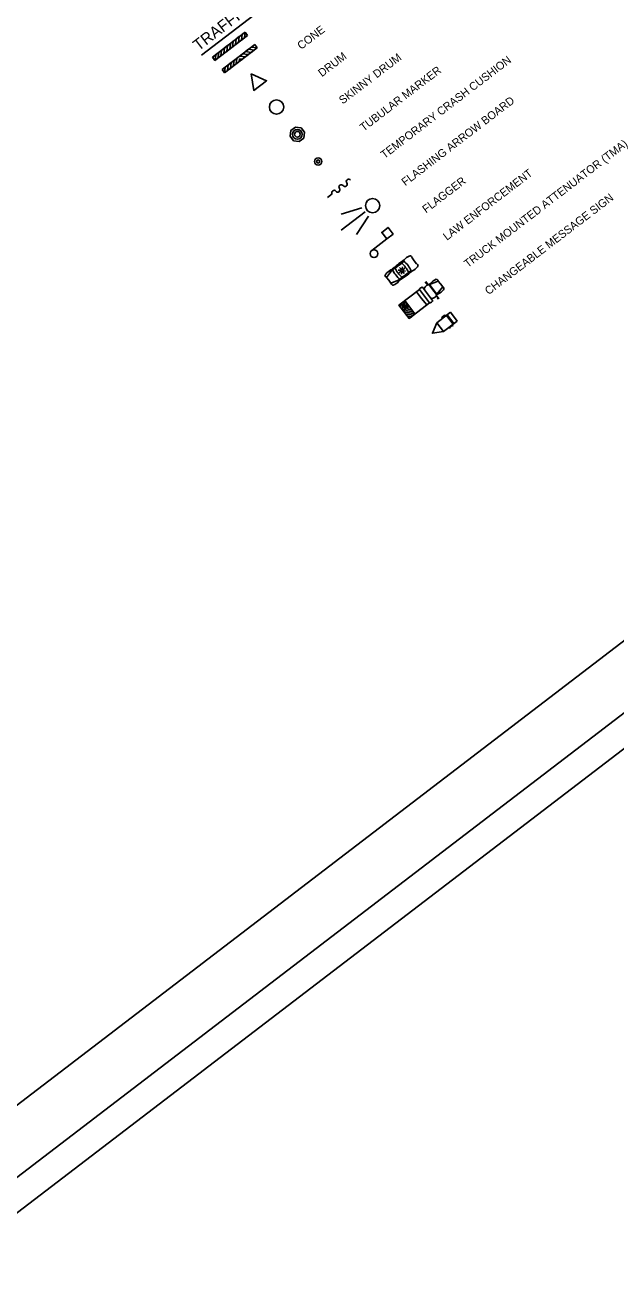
# Model space of a CAD drawing. Extents: x -642 to 2005, y -4412 to 1950.
# Drawn here: x 844 to 1361, y 126 to 1222 of the extents above; entities that cross this region are included whole.
import ezdxf

# ---------------------------------------------------------------- set-up
doc = ezdxf.new("R2010")
doc.units = 0
for name, color, linetype in [('DEV BORDER CELL', 7, 'Continuous'), ('Scratch_Level_0', 7, 'Continuous'), ('Sheet Plot Border Outside CELL', 7, 'Continuous')]:
    doc.layers.add(name, color=color, linetype=linetype)

msp = doc.modelspace()

# ---------------------------------------------------------------- linework, layer by layer
at = {"layer": 'DEV BORDER CELL'}
for p, q in [((998.1, 1195.3), (1161.9, 1320.5)), ((1007.8, 1193.5), (1036.3, 1215.3)), ((1038.5, 1212.5), (1009.9, 1190.6)), ((1022.8, 1200.4), (1023.4, 1205.4)), ((1023.4, 1205.4), (1026, 1207.4)), ((1026, 1207.4), (1025.4, 1202.4)), ((1028, 1204.4), (1028.6, 1209.4)), ((1030.5, 1206.3), (1028, 1204.4)), ((1028.6, 1209.4), (1031.2, 1211.4)), ((1031.2, 1211.4), (1030.5, 1206.3)), ((1033.1, 1208.3), (1033.8, 1213.4)), ((1035.7, 1210.3), (1033.1, 1208.3)), ((1033.8, 1213.4), (1036.3, 1215.3)), ((1036.3, 1215.3), (1035.7, 1210.3)), ((1036.3, 1215.3), (1038.5, 1212.5)), ((1007.8, 1193.5), (1010.6, 1195.6)), ((1010.6, 1195.6), (1010, 1190.6)), ((1012.5, 1192.6), (1013.2, 1197.6)), ((1015.1, 1194.5), (1012.5, 1192.6)), ((1013.2, 1197.6), (1015.7, 1199.5)), ((1015.7, 1199.5), (1015.1, 1194.5)), ((1016.1, 1182.6), (1044.7, 1204.4)), ((1017.7, 1196.5), (1018.3, 1201.5)), ((1020.2, 1198.5), (1017.7, 1196.5)), ((1018.3, 1201.5), (1020.9, 1203.5)), ((1046.9, 1201.6), (1018.3, 1179.7)), ((1020.9, 1203.5), (1020.2, 1198.5)), ((1025.4, 1202.4), (1022.8, 1200.4)), ((1034.1, 1196.4), (1031.6, 1194.4)), ((1031.6, 1194.4), (1036.6, 1193.7)), ((1039.1, 1195.7), (1034.1, 1196.4)), ((1036.6, 1193.7), (1039.1, 1195.7)), ((1039.3, 1200.3), (1036.7, 1198.3)), ((1036.7, 1198.3), (1041.7, 1197.6)), ((1044.3, 1199.6), (1039.3, 1200.3)), ((1041.7, 1197.6), (1044.3, 1199.6)), ((1044.7, 1204.4), (1041.9, 1202.3)), ((1041.9, 1202.3), (1046.9, 1201.6)), ((1044.7, 1204.4), (1046.9, 1201.6)), ((1046.9, 1201.6), (1044.7, 1204.4)), ((1010, 1190.6), (1007.8, 1193.5)), ((1009.9, 1190.6), (1007.8, 1193.5)), ((1016.1, 1182.6), (1018.9, 1184.7)), ((1018.9, 1184.7), (1018.3, 1179.7)), ((1020.9, 1181.7), (1021.5, 1186.7)), ((1023.4, 1183.6), (1020.9, 1181.7)), ((1021.5, 1186.7), (1024.1, 1188.7)), ((1024.1, 1188.7), (1023.4, 1183.6)), ((1026, 1185.6), (1026.6, 1190.6)), ((1028.6, 1187.6), (1026, 1185.6)), ((1026.6, 1190.6), (1029.2, 1192.6)), ((1029.2, 1192.6), (1028.6, 1187.6)), ((1031.1, 1189.5), (1031.5, 1192.1)), ((1033.7, 1191.5), (1031.1, 1189.5)), ((1031.4, 1189.8), (1034, 1191.7)), ((1031.5, 1192.1), (1034, 1191.7)), ((1018.3, 1179.7), (1016.1, 1182.6)), ((1018.3, 1179.7), (1016.1, 1182.6)), ((1108.5, 1070.8), (1112.5, 1073.8)), ((1138.5, 1061.8), (1120.2, 1056)), ((1141.3, 1058.1), (1120.3, 1042)), ((1144.1, 1054.4), (1133.8, 1038.3)), ((1147, 1024.3), (1160.2, 1034.5)), ((1165.1, 1007.7), (1167.5, 1008.8)), ((1172.7, 1007.9), (1171.4, 1009.5)), ((1175, 1015.2), (1173.3, 1013.2)), ((1173.6, 1008.2), (1173.9, 1010.2)), ((1174.3, 1014.9), (1174.5, 1014.6)), ((1174.5, 1007.7), (1176.1, 1008.9)), ((1184.3, 1015.4), (1182.3, 1017.9)), ((1184.3, 1015.4), (1186.2, 1012.8)), ((1165.1, 1007.7), (1160, 1000.9)), ((1161.9, 998.3), (1160, 1000.9)), ((1161.9, 998.3), (1163.9, 995.8)), ((1171.8, 999), (1163.9, 995.8)), ((1172.2, 1007.1), (1170.2, 1007.3)), ((1172.4, 1006.1), (1170.8, 1004.9)), ((1171.8, 999), (1173.5, 1001)), ((1173.3, 1005.6), (1173, 1003.6)), ((1174.2, 1005.9), (1175.5, 1004.3)), ((1174.7, 1006.7), (1176.7, 1006.4)), ((1181.6, 1006.5), (1179.3, 1005.4)), ((1181, 1006.2), (1181.2, 1006)), ((1181, 1006.2), (1181.2, 1006)), ((1196.2, 994.3), (1194.1, 997.1)), ((1196.4, 994.4), (1194.3, 997.2)), ((1197.7, 994.5), (1205.3, 997.6)), ((1207.2, 995.1), (1205.3, 997.6)), ((1170.9, 976.5), (1188.8, 990.2)), ((1190.7, 982.5), (1186.3, 988.3)), ((1193.2, 984.4), (1188.8, 990.2)), ((1195.9, 986.5), (1191.5, 992.3)), ((1194.9, 995.5), (1193.8, 996.9)), ((1195.9, 986.5), (1200.3, 980.7)), ((1200.5, 990), (1197.3, 994.2)), ((1200.9, 990.3), (1197.7, 994.5)), ((1200.5, 990), (1203.7, 985.8)), ((1200.9, 990.3), (1204.1, 986.2)), ((1204.1, 986.2), (1209.1, 992.7)), ((1207.2, 995.1), (1209.1, 992.7)), ((1170.9, 976.5), (1172.9, 978)), ((1179.7, 965), (1170.9, 976.5)), ((1170.9, 976.5), (1172.6, 974.3)), ((1172.9, 978), (1172.6, 974.3)), ((1173.9, 972.5), (1174.5, 979.3)), ((1174.5, 979.3), (1176, 980.5)), ((1176, 980.5), (1175.3, 970.8)), ((1184.8, 968.9), (1176, 980.5)), ((1176.9, 972), (1177.4, 978.7)), ((1177.4, 978.7), (1178.7, 976.9)), ((1178.7, 976.9), (1178.5, 973.2)), ((1179.7, 965), (1197.6, 978.6)), ((1190.7, 982.5), (1195.2, 976.8)), ((1193.2, 984.4), (1197.6, 978.6)), ((1203.5, 984.7), (1205.6, 982)), ((1203.7, 984.9), (1205.8, 982.1)), ((1204.3, 983.2), (1205.4, 981.8)), ((1175.3, 970.8), (1173.9, 972.5)), ((1175.3, 970.8), (1184.8, 968.9)), ((1176.6, 969), (1175.3, 970.8)), ((1183.3, 967.7), (1176.6, 969)), ((1183.4, 970.7), (1176.9, 972)), ((1178, 967.2), (1179.7, 965)), ((1181.7, 966.5), (1178, 967.2)), ((1178.5, 973.2), (1182.1, 972.5)), ((1179.7, 965), (1181.7, 966.5)), ((1182.1, 972.5), (1183.4, 970.7)), ((1184.8, 968.9), (1183.3, 967.7)), ((1215.9, 970.3), (1204, 961.1)), ((1210.8, 967.7), (1208.3, 965.8)), ((1211.3, 967), (1208.8, 965.1)), ((1212.5, 967.6), (1218.4, 959.9)), ((1213.1, 968.1), (1219, 960.4)), ((1215.9, 970.3), (1221.8, 962.5)), ((1221.8, 962.5), (1215.9, 970.3)), ((1204, 961.1), (1200.3, 952.2)), ((1209.9, 953.4), (1200.3, 952.2)), ((1204, 961.1), (1209.9, 953.4)), ((1221.8, 962.5), (1209.9, 953.4)), ((1217.5, 958.9), (1215, 957))]:
    msp.add_line(p, q, dxfattribs=at)
for points in [[(1331.7, 1914.5), (140.1, 1003.4), (777.9, 169.3), (1969.5, 1080.4)], [(1041.6, 1178.8), (1043.9, 1164.3), (1055.1, 1172.8)], [(1078.7, 1120.4), (1075.7, 1124.3), (1076.4, 1129.3), (1080.3, 1132.3), (1085.2, 1131.6), (1088.3, 1127.7), (1087.6, 1122.7), (1083.7, 1119.7)], [(1160.2, 1034.5), (1155.8, 1040.2), (1161.4, 1044.5), (1165.8, 1038.7)], [(1172.6, 974.3), (1170.9, 976.5), (1172.9, 978)], [(1174.5, 979.3), (1173.9, 972.5), (1176.6, 969), (1183.3, 967.7), (1184.8, 968.9), (1175.3, 970.8), (1176, 980.5)], [(1183.4, 970.7), (1176.9, 972), (1177.4, 978.7), (1178.7, 976.9), (1178.5, 973.2), (1182.1, 972.5)], [(1178, 967.2), (1181.7, 966.5), (1179.7, 965)]]:
    msp.add_lwpolyline(points, close=True, dxfattribs=at)
for centre, radius in [((1063.8, 1149.8), 6.25), ((1082, 1126), 4.31), ((1082, 1126), 2.5), ((1100.2, 1102.2), 3.13), ((1100.2, 1102.2), 1.33), ((1147.8, 1063.6), 6.25), ((1149, 1021.6), 3.37), ((1173.5, 1006.9), 1.01), ((1200.2, 952.1), 0.0857)]:
    msp.add_circle(centre, radius, dxfattribs=at)
for centre, radius, start, end in [((1126.8, 1084.7), 2, 37.3638, 217.3638), ((1114.1, 1075), 2, 37.3638, 217.3638), ((1117.2, 1077.4), 2, 217.3638, 37.3638), ((1120.4, 1079.9), 2, 37.3638, 217.3638), ((1123.6, 1082.3), 2, 217.3638, 37.3638), ((1180.1, 1017.6), 2.28, 9.2438, 65.4837), ((1209, 961.9), 63.7, 122.5167, 133.9587), ((1201.6, 970.2), 51.5, 123.2817, 131.4458), ((1188.6, 1018.7), 23.3, 205.1962, 229.5314), ((1158.2, 995.5), 23.3, 25.1962, 49.5314), ((1158.2, 995.5), 25.9, 25.1962, 49.5314), ((1185.3, 1010.8), 2.28, 9.2438, 65.4837), ((1160.9, 1003), 2.28, 189.2438, 245.4837), ((1188.6, 1018.7), 25.9, 205.1962, 229.5314), ((1139.2, 1053.4), 63.7, 300.7689, 312.1013), ((1143.8, 1045.9), 53.9, 303.4638, 311.2638), ((1203.1, 997.2), 2.18, 9.2438, 65.4837), ((1166.1, 996.2), 2.28, 189.2438, 245.4837), ((1208.1, 990.7), 2.18, 9.2438, 65.4837), ((1209, 965.8), 0.717, 179.4521, 255.2754), ((1210.6, 967), 0.717, 359.4521, 75.2754), ((1215.8, 957), 0.717, 179.4521, 255.2754), ((1217.3, 958.2), 0.717, 359.4521, 75.2754)]:
    msp.add_arc(centre, radius, start, end, dxfattribs=at)
for centre, major_axis, ratio, start_param, end_param in [((1177.7, 1017.2), (3.29, 2.45), 0.2034, 0, 2.945373), ((1161.9, 1005.1), (-3.23, -2.53), 0.2034, 3.141593, 6.283185), ((1184.3, 1008.6), (3.23, 2.53), 0.2034, 3.331712, 6.283185), ((1168.5, 996.5), (-3.29, -2.45), 0.2034, 0, 3.141593), ((1200.9, 996.8), (3.16, 2.35), 0.2034, 0, 3.141593), ((1190.2, 991.3), (1.37, 1.05), 0.269913, 0, 3.141593), ((1195.3, 992.2), (2.08, 2.04), 0.503092, 0, 3.141593), ((1207.2, 988.6), (3.1, 2.43), 0.2034, 3.141593, 6.283185), ((1199, 979.7), (1.37, 1.05), 0.269913, 3.141593, 6.283185), ((1201.2, 984.4), (2.51, 1.47), 0.503092, 3.141593, 6.283185)]:
    msp.add_ellipse(centre, major_axis=major_axis, ratio=ratio, start_param=start_param, end_param=end_param, dxfattribs=at)
at = {"layer": 'Scratch_Level_0'}
msp.add_lwpolyline([(1322.3, 1844.4), (210.2, 994), (787.3, 239.4), (1485.4, 773.2), (1413.6, 867.2), (1827.6, 1183.7)], close=True, dxfattribs=at)
at = {"layer": 'Sheet Plot Border Outside CELL'}
msp.add_lwpolyline([(663.6, 50.4), (2004.5, 1075.8), (1336.4, 1949.6), (-4.5, 924.2)], close=True, dxfattribs=at)

# ---------------------------------------------------------------- texts
at = {"layer": 'DEV BORDER CELL'}
for s, height, p in [('TRAFFIC CONTROL DEVICES', 10, (995.6, 1198.4)), ('CONE', 7, (1085.3, 1199.7)), ('DRUM', 7, (1103.5, 1175.8)), ('SKINNY DRUM', 7, (1121.7, 1152)), ('TEMPORARY CRASH CUSHION', 7, (1158.2, 1104.3)), ('TUBULAR MARKER', 7, (1140, 1128.2)), ('FLASHING ARROW BOARD', 7, (1176.4, 1080.5)), ('TRUCK MOUNTED ATTENUATOR (TMA)', 7, (1231.1, 1009)), ('LAW ENFORCEMENT', 7, (1212.8, 1032.8)), ('FLAGGER', 7, (1194.6, 1056.7)), ('CHANGEABLE MESSAGE SIGN', 7, (1249.3, 985.2))]:
    msp.add_text(s, height=height, rotation=37.4042, dxfattribs=at).set_placement(p)

doc.saveas('drawing.dxf')
